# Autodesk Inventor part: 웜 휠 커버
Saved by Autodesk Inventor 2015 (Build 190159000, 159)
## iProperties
Created: 2025-06
Part Number: 웜 휠 커버
Material: 일반
Document SubType Name: Modeling
Designer: User
Density: 1 g/cm^3
Appearance: 기본값
Author: User
Author: jhkim
Creation Date: 2025-05-23
Sending System: Autodesk Inventor 2026
Preprocessor: ST-DEVELOPER v20.1
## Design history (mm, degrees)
node "웜 휠 커버1"
node "솔리드1"
node "기준1"
